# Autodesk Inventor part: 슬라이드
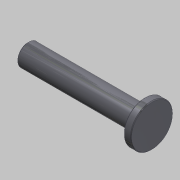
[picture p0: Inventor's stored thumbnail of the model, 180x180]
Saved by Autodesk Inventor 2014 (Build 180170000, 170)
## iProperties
Created: 2015-10
Part Number: 슬라이드
Document SubType Name: Modeling
Designer: mdu
Density: 1 g/cm^3
Material: 강철, 연강
Appearance: 강철 - 광택
Author: mdu
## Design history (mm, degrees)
sketch "스케치1"
  geometry: L1 (-75, 162)-(-75, 58) reference; L2 (-148, 110)-(22, 110); L3 (-148, 110)-(-148, 125); L4 (-148, 125)-(12, 125); L5 (12, 125)-(12, 139); L6 (12, 139)-(22, 139); L7 (22, 139)-(22, 110); 2 further points
  constraints: 12 end point, 3 parallel, 3 perpendicular, 1 midpoint, 1 point on line
  dimensions: "d0" = 58 diameter of L6 L2; "d1" = 30 diameter of L4 L2; "d2" = 10 distance of L5.end L6.end; "d3" = 170 distance of L2.start L2.end; "d4" = 73 distance between parallel lines of L3 L1
revolve "회전1" sketch "스케치1" stored, may be unused: angle "d5" = 90 deg
hole "구멍1" diameter "d11" = 13.376; stored, may be unused: countersink angle "d15" = 90 deg, drill point angle "d17" = 118 deg; dims "d9" = 10, "d10" = 10, "d12" = 22, "d13" = 4, "d14" = 2, "d16" = 25
chamfer "모따기1" distance "d6" = 1; stored, may be unused: second distance "d7" = 2, angle "d8" = 45 deg
node "솔리드1"
node "참조1"
